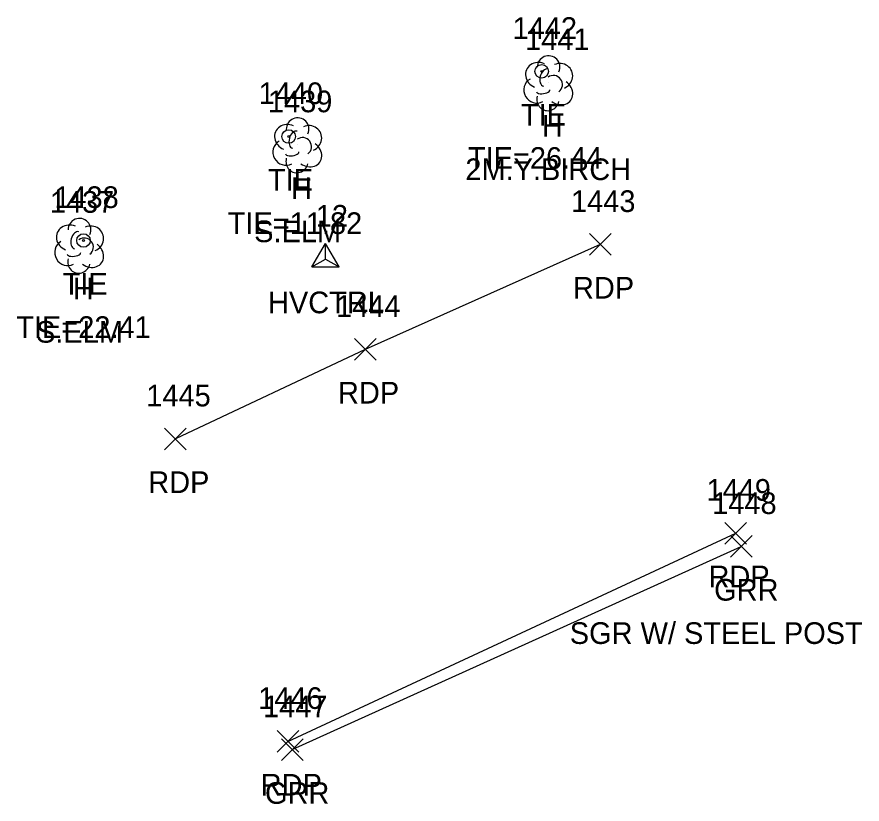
# Model space of a CAD drawing. Extents: x 1502119 to 1504100, y 606168 to 606406.
# Drawn here: x 1502119.2 to 1502197.3, y 606248.8 to 606321.5 of the extents above; entities that cross this region are included whole.
import ezdxf

# ---------------------------------------------------------------- set-up
doc = ezdxf.new("R2010")
doc.units = 0
for name, color, linetype in [('C_A', 7, 'Continuous'), ('C_C', 7, 'Continuous'), ('C_I', 7, 'Continuous'), ('CBP', 7, 'Continuous'), ('CPSM', 7, 'Continuous'), ('L_A', 7, 'Continuous'), ('L_C', 7, 'Continuous'), ('L_I', 7, 'Continuous'), ('LTD', 7, 'Continuous'), ('P_A', 7, 'Continuous'), ('P_I', 7, 'Continuous'), ('P_TIC', 7, 'Continuous'), ('PET', 7, 'Continuous'), ('R_A', 7, 'Continuous'), ('R_C', 7, 'Continuous'), ('R_I', 7, 'Continuous'), ('R_TIC', 7, 'Continuous'), ('RGR', 7, 'Continuous')]:
    doc.layers.add(name, color=color, linetype=linetype)

msp = doc.modelspace()

# ---------------------------------------------------------------- linework, layer by layer
at = {"layer": 'CBP'}
for centre, radius in [((1502167.702, 606316.435), 0.625), ((1502167.702, 606316.435), 0.0833), ((1502144.345, 606310.415), 0.625), ((1502144.345, 606310.415), 0.0833), ((1502125.394, 606300.816), 0.625), ((1502125.394, 606300.816), 0.0833)]:
    msp.add_circle(centre, radius, dxfattribs=at)
at = {"layer": 'CPSM'}
for p, q in [((1502146.487, 606298.375), (1502147.737, 606300.54)), ((1502148.987, 606298.375), (1502147.737, 606300.54)), ((1502147.737, 606299.096), (1502147.737, 606300.54)), ((1502146.487, 606298.375), (1502147.737, 606299.096)), ((1502147.737, 606299.096), (1502147.737, 606299.096)), ((1502147.737, 606299.096), (1502148.987, 606298.375)), ((1502146.487, 606298.375), (1502148.987, 606298.375))]:
    msp.add_line(p, q, dxfattribs=at)
at = {"layer": 'LTD'}
for p, q in [((1502168.287, 606315.393), (1502168.287, 606315.393)), ((1502168.287, 606315.393), (1502168.287, 606315.393)), ((1502145.121, 606309.66), (1502145.121, 606309.66)), ((1502145.121, 606309.66), (1502145.121, 606309.66)), ((1502124.981, 606300.378), (1502124.981, 606300.378)), ((1502124.981, 606300.378), (1502124.981, 606300.378))]:
    msp.add_line(p, q, dxfattribs=at)
for centre in [(1502168.334, 606316.827), (1502145.167, 606311.094), (1502125.028, 606301.812)]:
    msp.add_arc(centre, 1.047, 335.52715, 180.95627, dxfattribs=at)
for centre, major_axis, ratio, start_param, end_param in [((1502167.495, 606316.059), (1.21, -0.512), 0.895232, 1.570796, 4.712389), ((1502169.329, 606315.976), (-1.141, -0.483), 0.949671, 1.570796, 4.712389), ((1502168.079, 606315.851), (-0.208, -0.792), 0.645439, 3.141593, 6.283185), ((1502168.787, 606315.226), (-0.5, 0.667), 0.989748, 3.141593, 6.283185), ((1502167.204, 606314.684), (0.584, -1.042), 0.959034, 3.141593, 6.283185), ((1502169.287, 606314.56), (-1.09, 0.792), 0.841452, 1.570796, 4.712389), ((1502167.829, 606314.643), (-0.625, -0.083), 0.423636, 0, 3.141593), ((1502168.287, 606313.893), (0.265, 1.061), 0.942809, 1.570796, 4.712389), ((1502144.329, 606310.327), (1.21, -0.512), 0.895232, 1.570796, 4.712389), ((1502146.162, 606310.244), (-1.141, -0.483), 0.949671, 1.570796, 4.712389), ((1502144.912, 606310.119), (-0.208, -0.792), 0.645439, 3.141593, 6.283185), ((1502144.038, 606308.952), (0.584, -1.042), 0.959034, 3.141593, 6.283185), ((1502145.621, 606309.494), (-0.5, 0.667), 0.989748, 3.141593, 6.283185), ((1502146.121, 606308.827), (-1.09, 0.792), 0.841452, 1.570796, 4.712389), ((1502145.121, 606308.16), (0.265, 1.061), 0.942809, 1.570796, 4.712389), ((1502144.663, 606308.91), (-0.625, -0.083), 0.423636, 0, 3.141593), ((1502124.189, 606301.044), (1.21, -0.512), 0.895232, 1.570796, 4.712389), ((1502126.023, 606300.961), (-1.141, -0.483), 0.949671, 1.570796, 4.712389), ((1502124.773, 606300.836), (-0.208, -0.792), 0.645439, 3.141593, 6.283185), ((1502123.898, 606299.669), (0.584, -1.042), 0.959034, 3.141593, 6.283185), ((1502125.481, 606300.211), (-0.5, 0.667), 0.989748, 3.141593, 6.283185), ((1502125.981, 606299.545), (-1.09, 0.792), 0.841452, 1.570796, 4.712389), ((1502124.981, 606298.878), (0.265, 1.061), 0.942809, 1.570796, 4.712389), ((1502124.523, 606299.628), (-0.625, -0.083), 0.423636, 0, 3.141593)]:
    msp.add_ellipse(centre, major_axis=major_axis, ratio=ratio, start_param=start_param, end_param=end_param, dxfattribs=at)
at = {"layer": 'P_TIC'}
for points in [[(1502172.096, 606299.447), (1502174.096, 606301.447)], [(1502174.096, 606299.447), (1502172.096, 606301.447)], [(1502150.401, 606289.759), (1502152.401, 606291.759)], [(1502152.401, 606289.759), (1502150.401, 606291.759)], [(1502132.887, 606281.494), (1502134.887, 606283.494)], [(1502134.887, 606281.494), (1502132.887, 606283.494)], [(1502184.608, 606272.783), (1502186.608, 606274.783)], [(1502186.608, 606272.783), (1502184.608, 606274.783)], [(1502143.271, 606253.554), (1502145.271, 606255.554)], [(1502145.271, 606253.554), (1502143.271, 606255.554)]]:
    msp.add_lwpolyline(points, dxfattribs=at)
at = {"layer": 'PET'}
for points in [[(1502173.096, 606300.447), (1502151.401, 606290.759), (1502133.887, 606282.494)], [(1502144.271, 606254.554), (1502185.608, 606273.783)]]:
    msp.add_lwpolyline(points, dxfattribs=at)
at = {"layer": 'R_TIC'}
for points in [[(1502185.126, 606271.557), (1502187.126, 606273.557)], [(1502187.126, 606271.557), (1502185.126, 606273.557)], [(1502143.664, 606252.793), (1502145.664, 606254.793)], [(1502145.664, 606252.793), (1502143.664, 606254.793)]]:
    msp.add_lwpolyline(points, dxfattribs=at)
at = {"layer": 'RGR'}
msp.add_lwpolyline([(1502144.664, 606253.793), (1502186.126, 606272.557)], dxfattribs=at)

# ---------------------------------------------------------------- texts
at = {"layer": 'C_A'}
for s, p in [('TIE', (1502165.781, 606311.435)), ('TIE', (1502142.424, 606305.415)), ('TIE', (1502123.473, 606295.816)), ('HVCTRL', (1502142.43, 606294.096))]:
    msp.add_text(s, height=2, dxfattribs=at).set_placement(p)
at = {"layer": 'C_C'}
for s, p in [('TIE=26.44', (1502160.883, 606307.435)), ('TIE=11.82', (1502138.708, 606301.415)), ('TIE=22.41', (1502119.189, 606291.816))]:
    msp.add_text(s, height=2, dxfattribs=at).set_placement(p)
at = {"layer": 'C_I'}
for s, p in [('1442', (1502165.009, 606319.435)), ('1440', (1502141.566, 606313.415)), ('1438', (1502122.701, 606303.816)), ('12', (1502146.839, 606302.096))]:
    msp.add_text(s, height=2, dxfattribs=at).set_placement(p)
at = {"layer": 'L_A'}
for p in [(1502167.72, 606310.393), (1502144.554, 606304.66), (1502124.414, 606295.378)]:
    msp.add_text('H', height=2, dxfattribs=at).set_placement(p)
at = {"layer": 'L_C'}
for s, p in [('2M.Y.BIRCH', (1502160.649, 606306.393)), ('S.ELM', (1502141.152, 606300.66)), ('S.ELM', (1502121.013, 606291.378))]:
    msp.add_text(s, height=2, dxfattribs=at).set_placement(p)
at = {"layer": 'L_I'}
for s, p in [('1441', (1502166.161, 606318.393)), ('1439', (1502142.42, 606312.66)), ('1437', (1502122.288, 606303.378))]:
    msp.add_text(s, height=2, dxfattribs=at).set_placement(p)
at = {"layer": 'P_A'}
for p in [(1502170.584, 606295.447), (1502148.889, 606285.759), (1502131.375, 606277.494), (1502183.096, 606268.783), (1502141.759, 606249.554)]:
    msp.add_text('RDP', height=2, dxfattribs=at).set_placement(p)
at = {"layer": 'P_I'}
for s, p in [('1443', (1502170.403, 606303.447)), ('1444', (1502148.708, 606293.759)), ('1445', (1502131.194, 606285.494)), ('1449', (1502182.907, 606276.783)), ('1446', (1502141.523, 606257.554))]:
    msp.add_text(s, height=2, dxfattribs=at).set_placement(p)
at = {"layer": 'R_A'}
for p in [(1502183.614, 606267.557), (1502142.152, 606248.793)]:
    msp.add_text('GRR', height=2, dxfattribs=at).set_placement(p)
at = {"layer": 'R_C'}
msp.add_text('SGR W/ STEEL POST', height=2, dxfattribs=at).set_placement((1502170.291, 606263.557))
at = {"layer": 'R_I'}
for s, p in [('1448', (1502183.433, 606275.557)), ('1447', (1502141.971, 606256.793))]:
    msp.add_text(s, height=2, dxfattribs=at).set_placement(p)

doc.saveas('drawing.dxf')
